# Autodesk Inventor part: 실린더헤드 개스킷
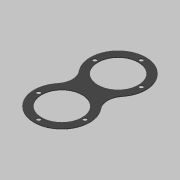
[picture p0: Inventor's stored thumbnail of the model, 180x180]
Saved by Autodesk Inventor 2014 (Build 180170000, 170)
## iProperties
Created: 2019-08
Part Number: 실린더헤드 개스킷
Material: 고무
Document SubType Name: Modeling
Designer: mduedu
Density: 1 g/cm^3
Appearance: 고무 - 검은색 - 버전 1.1
Author: mduedu
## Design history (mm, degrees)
sketch "스케치1"
  geometry: L1 (0, 0)-(0, 85); C1 r 30.5 at (0, 85); C2 r 30.5 at (0, 0); A1 r 42 centre (0, 0) between (0, 42) and (-32.469, 26.642); A2 r 42 centre (0, 85) between (0, 43) and (32.469, 58.358); A3 r 25 centre (51.795, 42.5) between (32.469, 58.358) and (32.469, 26.642); A4 r 25 centre (-51.795, 42.5) between (-32.469, 26.642) and (-32.469, 58.358); A5 r 42 centre (0, 0) between (32.469, 26.642) and (0, 42); A6 r 42 centre (0, 0) between (-32.469, 26.642) and (32.469, 26.642); A7 r 42 centre (0, 85) between (-32.469, 58.358) and (0, 43); A8 r 42 centre (0, 85) between (32.469, 58.358) and (-32.469, 58.358); A9 r 25 centre (51.795, 42.5) between (32.469, 26.642) and (32.469, 58.358); A10 r 25 centre (-51.795, 42.5) between (-32.469, 58.358) and (-32.469, 26.642); 1 further point
  constraints: 20 point on circle, 12 centre point, 4 coincident, 4 tangent, 2 end point, 2 point on line, 1 vertical
  dimensions: "d1" = 84 diameter of A1; "d3" = 85 distance of L1.start L1.end; "d4" = 84 diameter of A2; "d5" = 50 diameter of A3; "d6" = 50 diameter of A4 (= d5); "d11" = 61 diameter of C1; "d12" = 61 diameter of C2
extrude "돌출2" new body sketch "스케치1" distance "d13" = 1; taper "d14" = 0 deg
sketch "스케치2"
  geometry: A1 r 35 centre (0, 0) between (-35, 0) and (0, 35); 2 further points
  constraints: 3 point on circle, 2 horizontal alignment, 1 centre point, 1 coincident, 1 vertical alignment
  dimensions: "d15" = 70 diameter of A1
hole "구멍1" sketch "스케치2" at (-35, 0), (0, 35), (35, 0) diameter "d16" = 6; stored, may be unused: countersink angle "d20" = 90 deg, drill point angle "d22" = 118 deg; dims "d17" = 6, "d18" = 4, "d19" = 2, "d21" = 8
node "작업 평면1"
mirror "대칭1"
node "솔리드2"
other parameters: "d23" = 42.5
